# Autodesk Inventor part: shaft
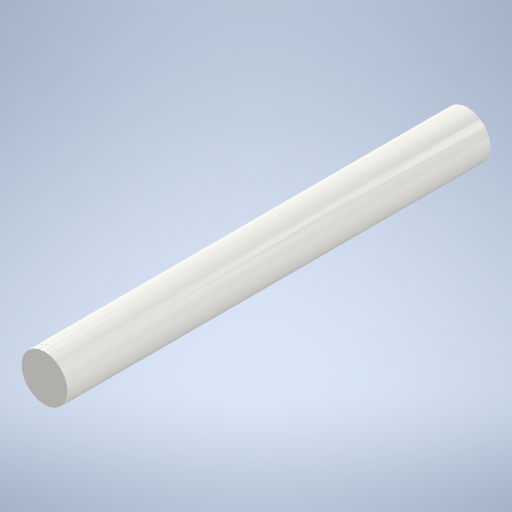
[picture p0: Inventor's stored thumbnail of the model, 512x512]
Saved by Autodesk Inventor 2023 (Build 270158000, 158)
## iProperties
Created: 2023-02
Part Number: shaft
Material: Stal
Document SubType Name: Modeling
Designer: Admin
Density: 7.85 g/cm^3
Appearance: Stal
Mass: 94.1378 g
Surface Area: 45.2327 cm^2
Volume: 11.9921 cm^3
Author: Admin
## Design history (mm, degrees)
sketch "Szkic1"
  geometry: C1 r 6 at (0, 0); 1 further point
  constraints: 1 centre point, 1 coincident
  dimensions: "d0" = 12 diameter of C1
extrude "Wyciągnięcie proste1" new body sketch "Szkic1" distance "d1" = 110; taper "d2" = 0 deg
sketch "Szkic6"
  geometry: C1 r 5.975 at (0, 0); C2 r 6 at (0, 0); 1 further point
  constraints: 2 centre point, 2 coincident
  dimensions: "d11" = 11.95 diameter of C1; "d12" = 12 diameter of C2
extrude "Wyciągnięcie proste4" cut sketch "Szkic6" distance "d13" = 2; taper "d14" = 0 deg
sketch "Szkic7"
  geometry: C1 r 5.975 at (0, 0) reference; C2 r 4 at (0, 0); C3 r 6 at (0, 0) reference; C4 r 6 at (0, 0); 1 further point
  constraints: 2 centre point, 2 coincident
  dimensions: "d17" = 11.95 diameter of C1 (derived)
extrude "Wyciągnięcie proste5" cut sketch "Szkic7" distance "d15" = 2; taper "d16" = 0 deg
node "Bryła1"
